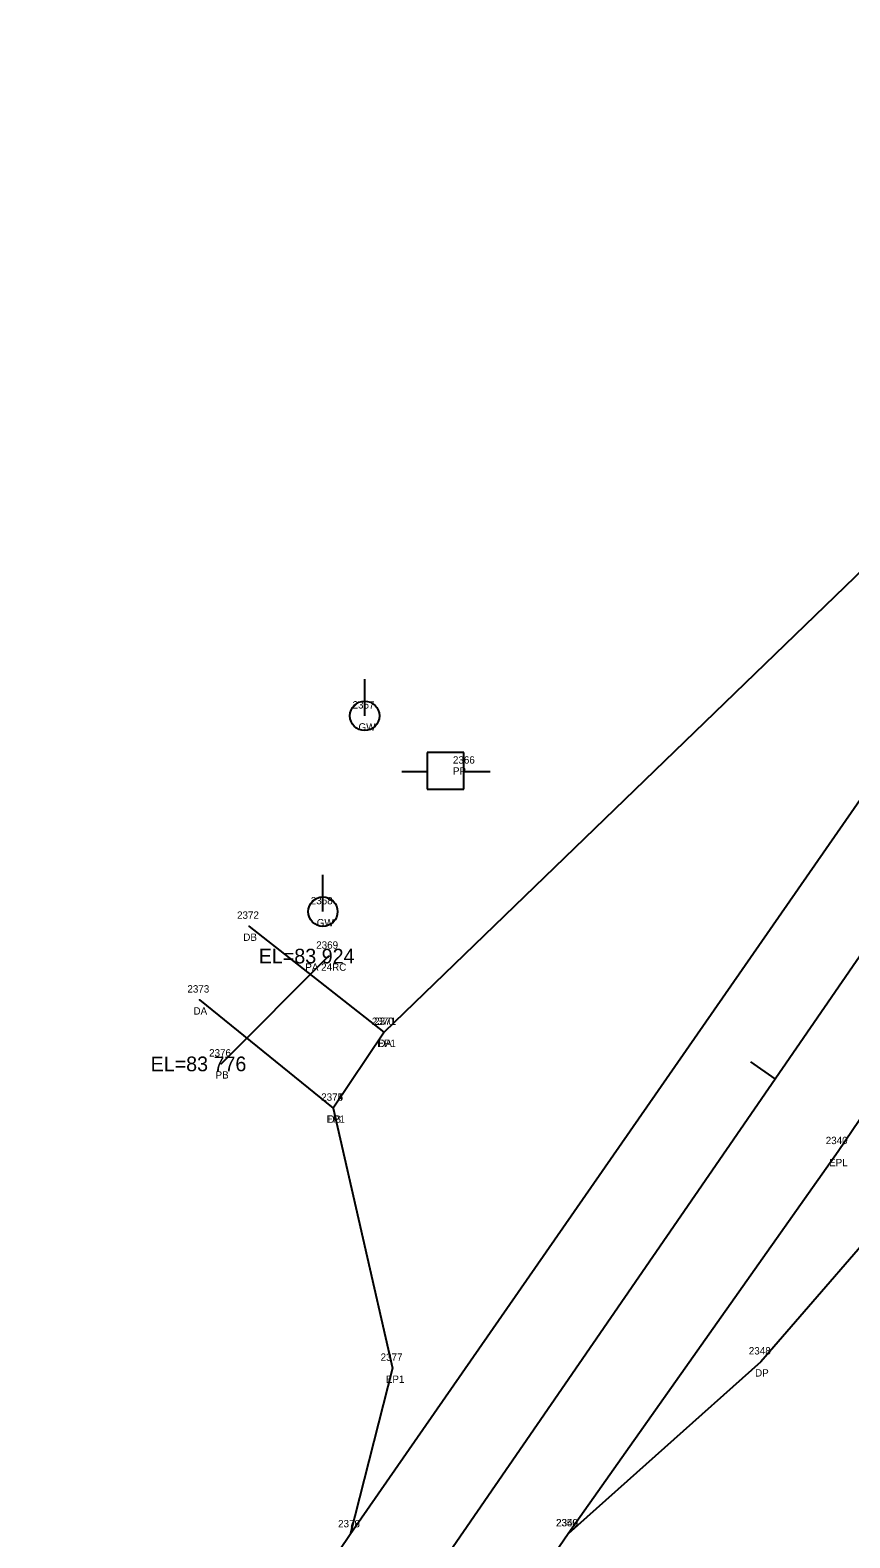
# Model space of a CAD drawing. Extents: x 2266664 to 2272542, y 716533 to 724777.
# Drawn here: x 2271334 to 2271445.4, y 723355.6 to 723560.6 of the extents above; entities that cross this region are included whole.
import ezdxf

# ---------------------------------------------------------------- set-up
doc = ezdxf.new("R2010")
doc.units = 0
for name, color, linetype in [('RD_EX_DR_Pipe', 7, 'Continuous'), ('RD_EX_DR_Pipe_txCode', 7, 'Continuous'), ('RD_EX_Driveway', 7, 'Continuous'), ('RD_EX_Driveway_txCode', 7, 'Continuous'), ('RD_EX_Road', 7, 'Continuous'), ('RD_EX_Road_txCode', 7, 'Continuous'), ('RD_EX_UT', 7, 'Continuous'), ('RD_EX_UT_txCode', 7, 'Continuous'), ('RD_HC_Cl', 7, 'Continuous'), ('RD_HC_Data_Tic', 7, 'Continuous'), ('RD_SMD_Locator', 7, 'Continuous'), ('RD_TX_Pipe_ElevEX', 7, 'Continuous')]:
    doc.layers.add(name, color=color, linetype=linetype)

msp = doc.modelspace()

# ---------------------------------------------------------------- linework, layer by layer
at = {"layer": 'RD_EX_DR_Pipe'}
msp.add_line((2271374.5, 723434.74), (2271359.95, 723420.08), dxfattribs=at)
at = {"layer": 'RD_EX_Driveway'}
for p, q in [((2271382.08, 723424.38), (2271363.72, 723438.81)), ((2271356.97, 723428.78), (2271375.15, 723414.07))]:
    msp.add_line(p, q, dxfattribs=at)
msp.add_lwpolyline([(2271561.71, 723471.33), (2271533.81, 723491.49), (2271519.19, 723500.22), (2271489.22, 723456.09), (2271462.24, 723415.94), (2271476.12, 723404.59), (2271469.28, 723395.41), (2271454.17, 723403.69), (2271433.28, 723379.57), (2271407.1, 723356.2)], dxfattribs=at)
at = {"layer": 'RD_EX_Road'}
for points in [[(2271604.53, 723684.77), (2271550.65, 723606.61), (2271518.33, 723560.15), (2271484.03, 723509.64), (2271377.45, 723356.07), (2271354.74, 723322.34), (2271292.52, 723232.43), (2271237.2, 723151.69), (2271183.29, 723072.86), (2271144.18, 723016.57), (2271140.21, 723010.22), (2271130.75, 722996.02)], [(2271614.21, 723655.35), (2271570.62, 723593.07), (2271532.38, 723537.1), (2271480.53, 723462.42), (2271443.77, 723408.17), (2271407.1, 723356.2), (2271374.69, 723308.79), (2271312.42, 723217.53), (2271256.65, 723136.94), (2271202.38, 723058.06), (2271164.68, 723002.43), (2271160.3, 722996.7), (2271150.37, 722982.5)], [(2271518.33, 723560.15), (2271503.23, 723541.79), (2271477.38, 723516.53), (2271382.08, 723424.38), (2271375.15, 723414.07), (2271383.23, 723378.71), (2271377.45, 723356.07)]]:
    msp.add_lwpolyline(points, dxfattribs=at)
at = {"layer": 'RD_EX_UT'}
for p, q in [((2271379.44, 723467.4), (2271379.44, 723472.4)), ((2271392.92, 723462.42), (2271387.92, 723462.42)), ((2271387.92, 723462.42), (2271387.92, 723457.42)), ((2271392.92, 723457.42), (2271392.92, 723462.42)), ((2271384.49, 723459.85), (2271387.95, 723459.85)), ((2271392.85, 723459.85), (2271396.49, 723459.85)), ((2271387.92, 723457.42), (2271392.92, 723457.42)), ((2271373.76, 723440.78), (2271373.76, 723445.78))]:
    msp.add_line(p, q, dxfattribs=at)
for centre in [(2271379.44, 723467.4), (2271373.76, 723440.78)]:
    msp.add_circle(centre, 2, dxfattribs=at)
at = {"layer": 'RD_HC_Cl'}
msp.add_line((2267342.91, 717471.2), (2272360.46, 724762.59), dxfattribs=at)
at = {"layer": 'RD_HC_Data_Tic'}
msp.add_line((2271435.23, 723418.07), (2271431.93, 723420.34), dxfattribs=at)
at = {"layer": 'RD_SMD_Locator'}
for centre in [(2271363.72, 723438.81), (2271374.5, 723434.74), (2271356.97, 723428.78), (2271382.08, 723424.38), (2271382.08, 723424.38), (2271359.95, 723420.08), (2271375.15, 723414.07), (2271375.15, 723414.07), (2271443.77, 723408.17), (2271383.23, 723378.71), (2271433.28, 723379.57), (2271377.45, 723356.07), (2271377.45, 723356.07), (2271407.1, 723356.2), (2271407.1, 723356.2)]:
    msp.add_circle(centre, 0.001, dxfattribs=at)

# ---------------------------------------------------------------- texts
at = {"layer": 'RD_EX_DR_Pipe_txCode'}
for s, p in [('2369', (2271372.85, 723435.74)), ('PA 24RC', (2271371.37, 723432.74)), ('2376', (2271358.29, 723421.08)), ('PB', (2271359.17, 723418.08))]:
    msp.add_text(s, height=1, dxfattribs=at).set_placement(p)
at = {"layer": 'RD_EX_Driveway_txCode'}
for s, p in [('2372', (2271362.09, 723439.81)), ('DB', (2271362.94, 723436.81)), ('2373', (2271355.34, 723429.78)), ('DA', (2271356.17, 723426.78)), ('2371', (2271380.73, 723425.38)), ('DA', (2271381.28, 723422.38)), ('2374', (2271373.53, 723415.07)), ('DB', (2271374.38, 723412.07)), ('2348', (2271431.65, 723380.57)), ('DP', (2271432.5, 723377.57)), ('2349', (2271405.47, 723357.2))]:
    msp.add_text(s, height=1, dxfattribs=at).set_placement(p)
at = {"layer": 'RD_EX_Road_txCode'}
for s, p in [('2370', (2271380.41, 723425.38)), ('EP1', (2271381.16, 723422.38)), ('2375', (2271373.53, 723415.07)), ('EP1', (2271374.23, 723412.07)), ('2340', (2271442.1, 723409.17)), ('EPL', (2271442.56, 723406.17)), ('2377', (2271381.6, 723379.71)), ('EP1', (2271382.31, 723376.71)), ('2378', (2271375.82, 723357.07)), ('2379', (2271375.82, 723357.07)), ('2350', (2271405.43, 723357.2))]:
    msp.add_text(s, height=1, dxfattribs=at).set_placement(p)
at = {"layer": 'RD_EX_UT_txCode'}
for s, p in [('2367', (2271377.79, 723468.4)), ('GW', (2271378.6, 723465.4)), ('2366', (2271391.43, 723460.91)), ('PP', (2271391.43, 723459.41)), ('2368', (2271372.11, 723441.78)), ('GW', (2271372.92, 723438.78))]:
    msp.add_text(s, height=1, dxfattribs=at).set_placement(p)
at = {"layer": 'RD_TX_Pipe_ElevEX'}
for s, p in [('EL=83 924  ', (2271365.04, 723433.74)), ('EL=83 776  ', (2271350.34, 723419.08))]:
    msp.add_text(s, height=2, dxfattribs=at).set_placement(p)

doc.saveas('drawing.dxf')
